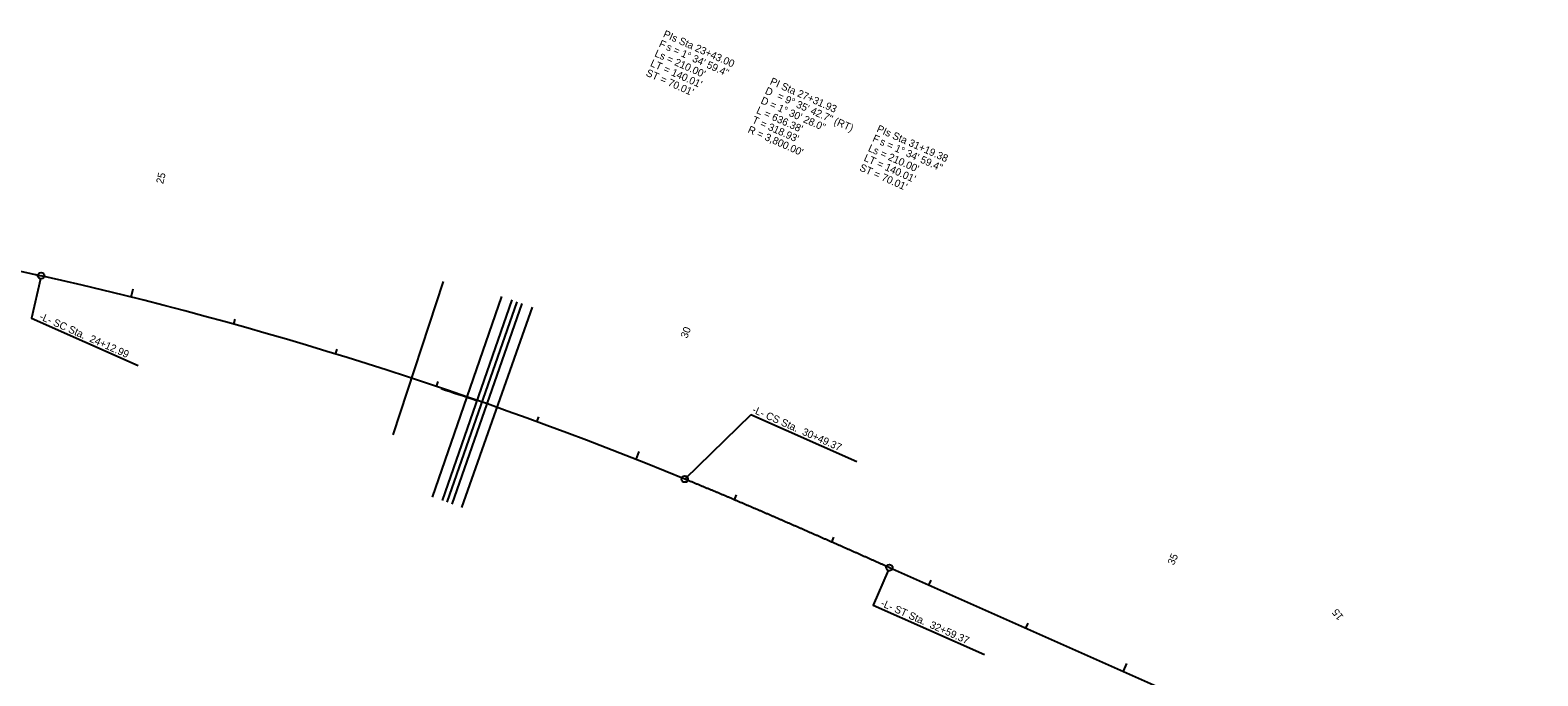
# Model space of a CAD drawing. Extents: x 1636713 to 1642889, y 841520 to 844630.
# Drawn here: x 1638092 to 1639512, y 843171 to 843778 of the extents above; entities that cross this region are included whole.
import ezdxf

# ---------------------------------------------------------------- set-up
doc = ezdxf.new("R2010")
doc.units = 0
for name, color, linetype in [('Exist 4 AWG with gnd feeder circuit in conduit', 7, 'Continuous'), ('Exist 6 AWG with gnd feeder circuit', 7, 'Continuous'), ('Exist 8 AWG with gnd feeder circuit', 7, 'Continuous'), ('Prop 2 AWG with gnd feeder circuit', 7, 'Continuous'), ('Prop 2 AWG with gnd feeder circuit in conduit', 7, 'Continuous'), ('Prop 4 AWG with gnd feeder circuit', 7, 'Continuous'), ('Prop Clearing and Grubbing', 7, 'Continuous')]:
    doc.layers.add(name, color=color, linetype=linetype)

msp = doc.modelspace()

# ---------------------------------------------------------------- linework, layer by layer
at = {"layer": 'Exist 6 AWG with gnd feeder circuit'}
msp.add_line((1638770.3, 843416.4), (1638708.2, 843355.8), dxfattribs=at)
for points in [[(1638101.4, 843544.4), (1638093, 843507.3), (1638193.6, 843462.7)], [(1638870.3, 843372), (1638770.3, 843416.4)], [(1638899.7, 843269.7), (1638885.5, 843237.3), (1638990.5, 843190.8)]]:
    msp.add_lwpolyline(points, dxfattribs=at)
for centre in [(1638102.1, 843547.3), (1638708.2, 843355.8), (1638900.9, 843272.5)]:
    msp.add_circle(centre, 3, dxfattribs=at)
at = {"layer": 'Exist 8 AWG with gnd feeder circuit'}
msp.add_line((1638900.9, 843272.5), (1640357.9, 842626.5), dxfattribs=at)
msp.add_arc((1637264.4, 839840.8), 3800, 67.6703, 77.2655, dxfattribs=at)
for points in [[(1637896.4, 843589.8), (1637899.2, 843589.3), (1637902, 843588.7), (1637904.8, 843588.2), (1637907.5, 843587.6), (1637910.3, 843587.1), (1637913.1, 843586.5), (1637915.9, 843586), (1637918.7, 843585.4), (1637921.5, 843584.9), (1637924.2, 843584.3), (1637927, 843583.8), (1637929.8, 843583.2), (1637932.6, 843582.7), (1637935.4, 843582.1), (1637938.2, 843581.6), (1637941, 843581), (1637943.7, 843580.5), (1637946.5, 843579.9), (1637949.3, 843579.4), (1637952.1, 843578.8), (1637954.9, 843578.3), (1637957.7, 843577.7), (1637960.4, 843577.1), (1637963.2, 843576.6), (1637966, 843576), (1637968.8, 843575.5), (1637971.6, 843574.9), (1637974.3, 843574.4), (1637977.1, 843573.8), (1637979.9, 843573.2), (1637982.7, 843572.7), (1637985.5, 843572.1), (1637988.3, 843571.5), (1637991, 843571), (1637993.8, 843570.4), (1637996.6, 843569.8), (1637999.4, 843569.3), (1638002.2, 843568.7), (1638004.9, 843568.1), (1638007.7, 843567.6), (1638010.5, 843567), (1638013.3, 843566.4), (1638016.1, 843565.9), (1638018.8, 843565.3), (1638021.6, 843564.7), (1638024.4, 843564.1), (1638027.2, 843563.5), (1638029.9, 843563), (1638032.7, 843562.4), (1638035.5, 843561.8), (1638038.3, 843561.2), (1638041.1, 843560.6), (1638043.8, 843560), (1638046.6, 843559.4), (1638049.4, 843558.9), (1638052.2, 843558.3), (1638054.9, 843557.7), (1638057.7, 843557.1), (1638060.5, 843556.5), (1638063.3, 843555.9), (1638066, 843555.3), (1638068.8, 843554.7), (1638071.6, 843554.1), (1638074.3, 843553.5), (1638077.1, 843552.9), (1638079.9, 843552.3), (1638082.7, 843551.6), (1638085.4, 843551), (1638088.2, 843550.4), (1638091, 843549.8), (1638093.7, 843549.2), (1638096.5, 843548.6), (1638099.3, 843547.9), (1638102.1, 843547.3)], [(1638900.9, 843272.5), (1638898.3, 843273.6), (1638895.7, 843274.8), (1638893.1, 843275.9), (1638890.5, 843277.1), (1638887.9, 843278.2), (1638885.3, 843279.4), (1638882.7, 843280.5), (1638880.1, 843281.7), (1638877.6, 843282.8), (1638875, 843284), (1638872.4, 843285.1), (1638869.8, 843286.3), (1638867.2, 843287.4), (1638864.6, 843288.6), (1638862, 843289.7), (1638859.4, 843290.9), (1638856.8, 843292), (1638854.2, 843293.2), (1638851.6, 843294.3), (1638849, 843295.5), (1638846.4, 843296.6), (1638843.8, 843297.7), (1638841.2, 843298.9), (1638838.6, 843300), (1638836, 843301.2), (1638833.4, 843302.3), (1638830.8, 843303.5), (1638828.2, 843304.6), (1638825.6, 843305.7), (1638823, 843306.9), (1638820.4, 843308), (1638817.8, 843309.2), (1638815.2, 843310.3), (1638812.6, 843311.4), (1638810, 843312.6), (1638807.4, 843313.7), (1638804.8, 843314.8), (1638802.2, 843316), (1638799.6, 843317.1), (1638797, 843318.2), (1638794.4, 843319.3), (1638791.8, 843320.5), (1638789.2, 843321.6), (1638786.6, 843322.7), (1638784, 843323.9), (1638781.4, 843325), (1638778.8, 843326.1), (1638776.2, 843327.2), (1638773.6, 843328.3), (1638771, 843329.5), (1638768.3, 843330.6), (1638765.7, 843331.7), (1638763.1, 843332.8), (1638760.5, 843333.9), (1638757.9, 843335), (1638755.3, 843336.1), (1638752.7, 843337.2), (1638750.1, 843338.4), (1638747.4, 843339.5), (1638744.8, 843340.6), (1638742.2, 843341.7), (1638739.6, 843342.8), (1638737, 843343.9), (1638734.4, 843345), (1638731.8, 843346.1), (1638729.1, 843347.1), (1638726.5, 843348.2), (1638723.9, 843349.3), (1638721.3, 843350.4), (1638718.7, 843351.5), (1638716, 843352.6), (1638713.4, 843353.7), (1638710.8, 843354.8), (1638708.2, 843355.8)]]:
    msp.add_spline(points, degree=3, dxfattribs=at)
at = {"layer": 'Prop 2 AWG with gnd feeder circuit in conduit'}
for p, q in [((1638186.7, 843527.2), (1638188.6, 843534.9)), ((1638662.4, 843374.3), (1638665.3, 843381.7)), ((1639124.1, 843182.3), (1639120.9, 843174.9))]:
    msp.add_line(p, q, dxfattribs=at)
at = {"layer": 'Prop 4 AWG with gnd feeder circuit'}
for p, q in [((1638283.4, 843501.6), (1638284.7, 843506.4)), ((1638379.3, 843473.5), (1638380.8, 843478.3)), ((1638474.5, 843442.9), (1638476.1, 843447.7)), ((1638568.9, 843409.9), (1638570.6, 843414.6)), ((1638754.9, 843336.3), (1638756.8, 843340.9)), ((1638846.6, 843296.5), (1638848.6, 843301.1)), ((1638938, 843256), (1638940.1, 843260.6)), ((1639029.5, 843215.5), (1639031.5, 843220.1))]:
    msp.add_line(p, q, dxfattribs=at)
at = {"layer": 'Prop Clearing and Grubbing'}
for p, q in [((1638480.8, 843542), (1638433.3, 843397.6)), ((1638535.5, 843527.8), (1638470.4, 843338.7)), ((1638545.2, 843524.5), (1638479.6, 843335.6)), ((1638550.1, 843522.8), (1638484.2, 843334)), ((1638554.9, 843521.1), (1638488.7, 843332.3)), ((1638564.6, 843517.7), (1638497.9, 843329.1)), ((1638502.9, 843433.3), (1638502.7, 843432.5)), ((1638512.4, 843430), (1638512.1, 843429.2)), ((1638516.8, 843427.6), (1638517.1, 843428.4)), ((1638531.3, 843423.4), (1638531, 843422.7))]:
    msp.add_line(p, q, dxfattribs=at)
msp.add_arc((1633961.4, 829662.3), 14500, 71.70853, 71.84781, dxfattribs=at)

# ---------------------------------------------------------------- texts
at = {"layer": 'Exist 4 AWG with gnd feeder circuit in conduit'}
for s, rotation, p in [('25', 75.9536, (1638216.9, 843633.3)), ('30', 68.4147, (1638710.4, 843487.8)), ('35', 66.0871, (1639168.8, 843274.3)), ('15', 127.8269, (1639329, 843226.3))]:
    msp.add_text(s, height=7, rotation=rotation, dxfattribs=at).set_placement(p)
at = {"layer": 'Exist 6 AWG with gnd feeder circuit'}
for s, p in [('-L- SC Sta.  24+12.99', (1638099.9, 843506.4)), ('-L- CS Sta.  30+49.37', (1638771, 843418.8)), ('-L- ST Sta.  32+59.37', (1638892.1, 843236.6))]:
    msp.add_text(s, height=7, rotation=336.0871, dxfattribs=at).set_placement(p)
at = {"layer": 'Prop 2 AWG with gnd feeder circuit'}
for s, p in [('F', (1638683.2, 843763.2)), ('PIs Sta 23+43.00', (1638687.2, 843772.4)), ("Ls = 210.00'", (1638679.1, 843754.1)), ('s = 1%%d 34\' 59.4"', (1638690, 843760.2)), ("ST = 70.01'", (1638671, 843735.8)), ("LT = 140.01'", (1638675.1, 843744.9)), ('D', (1638783.1, 843718.9)), ('PI Sta 27+31.93', (1638787.8, 843727.8)), ('D = 1%%d 30\' 28.0"', (1638779.1, 843709.8)), ('= 9%%d 35\' 42.7" (RT)', (1638794.5, 843714)), ("T = 318.93'", (1638770.9, 843691.5)), ("L = 636.38'", (1638775, 843700.6)), ("R = 3,800.00'", (1638766.9, 843682.4)), ('PIs Sta 31+19.38', (1638888.3, 843683.2)), ("Ls = 210.00'", (1638880.2, 843664.9)), ('F', (1638884.3, 843674.1)), ('s = 1%%d 34\' 59.4"', (1638891.2, 843671)), ("ST = 70.01'", (1638872.1, 843646.6)), ("LT = 140.01'", (1638876.2, 843655.8))]:
    msp.add_text(s, height=7, rotation=336.0871, dxfattribs=at).set_placement(p)

doc.saveas('drawing.dxf')
